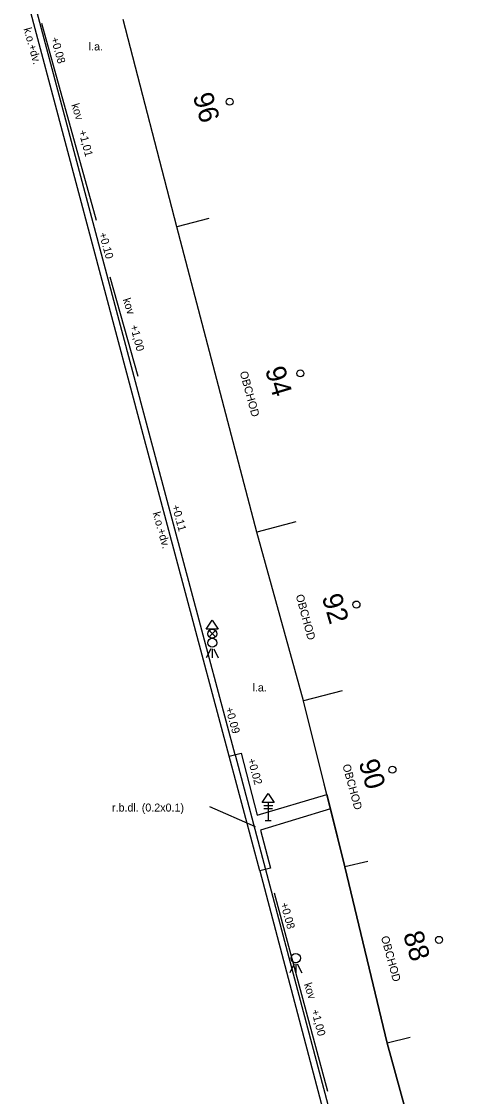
# Model space of a CAD drawing. Extents: x -598845 to -598697, y -1157541 to -1157331.
# Drawn here: x -598791 to -598768.5, y -1157430.4 to -1157376.7 of the extents above; entities that cross this region are included whole.
import ezdxf

# ---------------------------------------------------------------- set-up
doc = ezdxf.new("R2010")
doc.units = 0
for name, color, linetype in [('Vrstva 15', 7, 'Continuous'), ('Vrstva 22', 7, 'Continuous'), ('Vrstva 4', 7, 'Continuous'), ('Vrstva 43', 7, 'Continuous'), ('Vrstva 44', 7, 'Continuous'), ('Vrstva 49', 7, 'Continuous'), ('Vrstva 50', 7, 'Continuous'), ('Vrstva 63', 7, 'Continuous'), ('Vrstva 7', 7, 'Continuous')]:
    doc.layers.add(name, color=color, linetype=linetype)

msp = doc.modelspace()

# ---------------------------------------------------------------- linework, layer by layer
at = {"layer": 'Vrstva 15'}
for centre in [(-598780.616, -1157380.688), (-598777.078, -1157394.268), (-598774.277, -1157405.823), (-598772.477, -1157414.083), (-598770.152, -1157422.588)]:
    msp.add_circle(centre, 0.175, dxfattribs=at)
at = {"layer": 'Vrstva 22'}
for p, q in [((-598787.27, -1157386.62), (-598790, -1157376.77)), ((-598785.19, -1157394.42), (-598786.59, -1157389.46)), ((-598775.71, -1157430.16), (-598778.38, -1157420.26))]:
    msp.add_line(p, q, dxfattribs=at)
at = {"layer": 'Vrstva 4'}
for p, q in [((-598783.254, -1157386.942), (-598785.94, -1157376.582)), ((-598781.656, -1157386.528), (-598783.254, -1157386.942)), ((-598779.25, -1157402.201), (-598783.254, -1157386.942)), ((-598777.305, -1157401.691), (-598779.25, -1157402.201)), ((-598776.928, -1157410.64), (-598779.25, -1157402.201)), ((-598774.983, -1157410.13), (-598776.928, -1157410.64)), ((-598774.853, -1157418.939), (-598776.928, -1157410.64)), ((-598773.705, -1157418.664), (-598774.853, -1157418.939)), ((-598772.74, -1157427.75), (-598774.853, -1157418.939)), ((-598771.592, -1157427.475), (-598772.74, -1157427.75)), ((-598770.33, -1157436.597), (-598772.74, -1157427.75))]:
    msp.add_line(p, q, dxfattribs=at)
at = {"layer": 'Vrstva 44'}
for p, q in [((-598781.326, -1157407.126), (-598781.646, -1157407.446)), ((-598781.646, -1157407.126), (-598781.326, -1157407.446)), ((-598781.561, -1157408.036), (-598781.786, -1157408.486)), ((-598781.486, -1157408.036), (-598781.486, -1157408.486)), ((-598781.411, -1157408.036), (-598781.186, -1157408.486)), ((-598778.909, -1157415.871), (-598778.461, -1157415.871)), ((-598778.909, -1157416.021), (-598778.466, -1157416.021)), ((-598778.689, -1157415.721), (-598778.689, -1157416.621)), ((-598778.839, -1157416.621), (-598778.539, -1157416.621)), ((-598777.388, -1157423.791), (-598777.614, -1157424.243)), ((-598777.314, -1157423.793), (-598777.314, -1157424.243)), ((-598777.239, -1157423.791), (-598777.014, -1157424.243))]:
    msp.add_line(p, q, dxfattribs=at)
for points in [[(-598781.182, -1157407.055), (-598781.784, -1157407.055), (-598781.485, -1157406.598)], [(-598778.989, -1157415.721), (-598778.689, -1157415.266), (-598778.389, -1157415.721)]]:
    msp.add_lwpolyline(points, close=True, dxfattribs=at)
for centre, radius in [((-598781.486, -1157407.286), 0.226), ((-598781.486, -1157407.736), 0.224), ((-598777.314, -1157423.498), 0.234)]:
    msp.add_circle(centre, radius, dxfattribs=at)
at = {"layer": 'Vrstva 49'}
msp.add_line((-598781.626, -1157415.922), (-598779.341, -1157416.924), dxfattribs=at)
at = {"layer": 'Vrstva 63'}
for p, q in [((-598784.71, -1157397.003), (-598790.729, -1157374.377)), ((-598783.254, -1157386.942), (-598785.94, -1157376.582)), ((-598779.25, -1157402.201), (-598783.254, -1157386.942)), ((-598780.346, -1157413.332), (-598784.71, -1157397.003)), ((-598776.928, -1157410.64), (-598779.25, -1157402.201)), ((-598775.757, -1157415.324), (-598776.928, -1157410.64)), ((-598780.346, -1157413.332), (-598778.819, -1157419.064)), ((-598775.757, -1157415.324), (-598775.58, -1157416.03)), ((-598775.58, -1157416.03), (-598774.853, -1157418.939)), ((-598778.819, -1157419.064), (-598768.527, -1157457.927)), ((-598774.853, -1157418.939), (-598772.74, -1157427.75)), ((-598772.74, -1157427.75), (-598770.33, -1157436.597))]:
    msp.add_line(p, q, dxfattribs=at)
at = {"layer": 'Vrstva 7'}
for p, q in [((-598785, -1157397.08), (-598791.019, -1157374.454)), ((-598780.636, -1157413.409), (-598785, -1157397.08)), ((-598780.636, -1157413.409), (-598780.036, -1157413.25)), ((-598779.109, -1157419.141), (-598780.636, -1157413.409)), ((-598780.036, -1157413.25), (-598779.24, -1157416.35)), ((-598779.24, -1157416.35), (-598775.757, -1157415.324)), ((-598775.757, -1157415.324), (-598775.58, -1157416.03)), ((-598775.58, -1157416.03), (-598779.07, -1157417.1)), ((-598779.07, -1157417.1), (-598778.58, -1157419)), ((-598778.58, -1157419), (-598779.109, -1157419.141)), ((-598779.109, -1157419.141), (-598768.817, -1157458.003))]:
    msp.add_line(p, q, dxfattribs=at)

# ---------------------------------------------------------------- texts
at = {"layer": 'Vrstva 43'}
for s, p in [('96', (-598782.468, -1157380.395)), ('94', (-598778.854, -1157394.079)), ('92', (-598776.016, -1157405.446)), ('90', (-598774.178, -1157413.716)), ('88', (-598771.955, -1157422.31))]:
    msp.add_text(s, height=1, rotation=286.5472, dxfattribs=at).set_placement(p)
at = {"layer": 'Vrstva 49'}
for s, rotation, p in [('k.o.+dv.', 285.596, (-598790.92, -1157377.042)), ('kov', 288.043, (-598788.536, -1157380.846)), ('kov', 288.043, (-598785.964, -1157390.572)), ('OBCHOD', 285.2612, (-598780.115, -1157394.213)), ('k.o.+dv.', 285.596, (-598784.467, -1157401.246)), ('OBCHOD', 285.2612, (-598777.316, -1157405.371)), ('OBCHOD', 285.2612, (-598774.981, -1157413.859)), ('OBCHOD', 285.2612, (-598773.056, -1157422.449)), ('kov', 288.043, (-598776.909, -1157424.806))]:
    msp.add_text(s, height=0.4, rotation=rotation, dxfattribs=at).set_placement(p)
for s, p in [('l.a.', (-598787.658, -1157378.123)), ('l.a.', (-598779.471, -1157410.169)), ('r.b.dl. (0.2x0.1)', (-598786.494, -1157416.173))]:
    msp.add_text(s, height=0.4, dxfattribs=at).set_placement(p)
at = {"layer": 'Vrstva 50'}
for s, rotation, p in [('+0.08', 285.6364, (-598789.557, -1157377.517)), ('+1,01', 284.7294, (-598788.167, -1157382.16)), ('+0.10', 285.6364, (-598787.155, -1157387.276)), ('+1,00', 284.7294, (-598785.595, -1157391.886)), ('+0.11', 285.6364, (-598783.515, -1157400.895)), ('+0.09', 285.6364, (-598780.835, -1157411.011)), ('+0.02', 285.6364, (-598779.724, -1157413.571)), ('+0.08', 285.6364, (-598778.086, -1157420.78)), ('+1,00', 284.7294, (-598776.54, -1157426.12))]:
    msp.add_text(s, height=0.4, rotation=rotation, dxfattribs=at).set_placement(p)

doc.saveas('drawing.dxf')
